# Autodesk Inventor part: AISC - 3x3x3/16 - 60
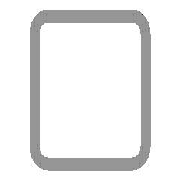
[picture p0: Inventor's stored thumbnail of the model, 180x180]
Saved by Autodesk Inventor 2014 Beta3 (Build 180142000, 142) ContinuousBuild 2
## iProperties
Created: 2010-11
Part Number: AISC - 3x3x3/16 - 60
Material: Steel, Mild
Description: Tube
Document SubType Name: Modeling
Standard: ANSI
Designer: Beta-8540w
Standards Organization: ANSI
Language: en-US
Size Designation: 3x3x3/16
Categories: <MemberInstance><Categories><Category DisplayName="Structural Shapes" InternalName="089c4875-fa83-4c05-b084-43b9cc11f5ed" Mnemonic="GRDR"><CategoryParameter Dis
Stock Number: 3x3x3/16
Density: 7.86 g/cm^3
Appearance: Steel
IsCustomPart: 1
_CCFamilyMember: 9
_CCFamilyDisplayName: ANSI AISC (Square) - Tube
_FrameMemberDoc: Frame Member File
_Version: 15.0.0
_GetPNFromCC: 1
G_L: 60.000 in
G_W: 3.000 in
G_H: 3.000 in
Author: Beta-8540w
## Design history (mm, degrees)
node "Start plane"
node "End plane"
sketch "Sketch"
  geometry: L1 (-38.1, -28.575)-(-38.1, 28.575); L2 (-28.575, 38.1)-(28.575, 38.1); L3 (38.1, 28.575)-(38.1, -28.575); L4 (28.575, -38.1)-(-28.575, -38.1); L5 (-28.575, 33.337)-(28.575, 33.338); L6 (33.338, 28.575)-(33.338, -28.575); L7 (28.575, -33.337)-(-28.575, -33.338); L8 (-33.338, -28.575)-(-33.338, 28.575); L9 (0, 56.102)-(0, -56.102) reference; L10 (-56.102, 0)-(56.102, 0) reference; A1 r 9.525 centre (-28.575, -28.575) between (-38.1, -28.575) and (-28.575, -38.1); A2 r 9.525 centre (-28.575, 28.575) between (-28.575, 38.1) and (-38.1, 28.575); A3 r 9.525 centre (28.575, 28.575) between (38.1, 28.575) and (28.575, 38.1); A4 r 9.525 centre (28.575, -28.575) between (28.575, -38.1) and (38.1, -28.575); A5 r 4.763 centre (-28.575, 28.575) between (-28.575, 33.337) and (-33.338, 28.575); A6 r 4.763 centre (28.575, 28.575) between (33.338, 28.575) and (28.575, 33.338); A7 r 4.763 centre (28.575, -28.575) between (28.575, -33.337) and (33.338, -28.575); A8 r 4.763 centre (-28.575, -28.575) between (-33.338, -28.575) and (-28.575, -33.338)
  constraints: 16 end point, 16 point on circle, 8 centre point, 8 tangent, 4 parallel, 3 equal radius, 2 perpendicular, 7 other
  dimensions: "d10" = 76.2 distance between parallel lines of L2 L4 (= G_H); "d11" = 76.2 distance between parallel lines of L1 L3 (= G_W); "d12" = 4.7625 distance between parallel lines of L3 L6 (= G_T); "d15" = 38.1 distance between parallel lines of L2 L10 (= 0.5 x d10); "d16" = 38.1 distance between parallel lines of L9 L3 (= 0.5 x d11); "d17" = 9.525 radius of A1 (= G_IR)
extrude "Body" new body sketch "Sketch" stored distance "d3" = 1524 (= G_L); taper "d4" = 0 deg
node "Driven Length"
  sketch "Sketch3"
    geometry: L1 (0, 0)-(10, 0) reference
    constraints: 2 end point, 1 horizontal
  workplane "Work Plane3"
  sketch "Sketch4"
    geometry: L1 (-2, 0)-(12, 0) reference; L2 (-2, 1524)-(12, 1524) reference
    dimensions: "d19" = 1524 distance between parallel lines of L1 L2 (derived)
body "Solid1"
other parameters: "G_W" = 76.2 [user parameter; used in 1 equation term], "G_H" = 76.2 [user parameter; used in 1 equation term], "G_T" = 4.7625 [user parameter; used in 1 equation term], "G_IR" = 9.525 [user parameter; used in 1 equation term], "G_L" = 1524 (= d19) [user parameter; used in 1 equation term], "G_OFFSET_START" = 0 [user parameter; used in 1 equation term], "G_OFFSET_END" = 0 [user parameter; used in 1 equation term], "d13" = 0 (computed from G_OFFSET_START), "d14" = 1524 (= G_OFFSET_END + B_L), "B_L" = 1524 [user parameter; used in 1 equation term], "d18" = 90 deg
